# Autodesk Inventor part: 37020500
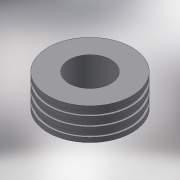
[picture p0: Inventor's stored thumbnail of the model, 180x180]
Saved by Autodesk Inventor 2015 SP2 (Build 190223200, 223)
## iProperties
Created: 2017-08
Part Number: 37020500
Material: Generic
Description: PLASSON MAN HOLE ADAPTOR 500
Document SubType Name: Modeling
Designer: Кирилл
Density: 1 g/cm^3
Appearance: Default
Author: Кирилл
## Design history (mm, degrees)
derived "37020-477207.ipt"
feature "Solid1::37020-477207.ipt"
tag "TaggingFeature1"
body "Solid1"
other parameters: "d0" = 135, "d1" = 651, "d2" = 618.45, "d3" = 441, "d6" = 54, "L_" = 135, "d_1" = 441, "D_" = 651, "H_" = 54
